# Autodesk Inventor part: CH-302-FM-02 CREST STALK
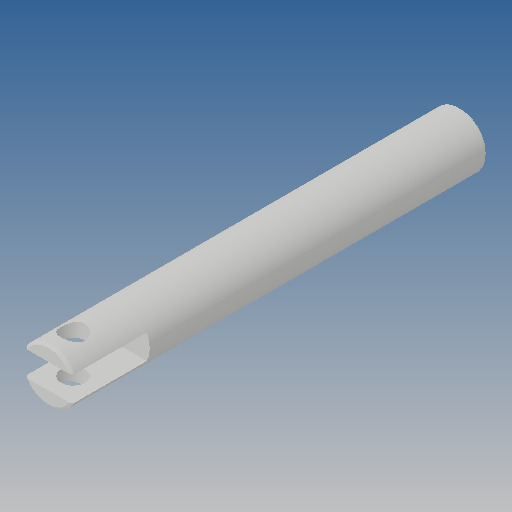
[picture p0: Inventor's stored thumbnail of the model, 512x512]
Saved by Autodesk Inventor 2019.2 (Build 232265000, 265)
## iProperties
Created: 2013-03
Part Number: CH-302-FM-02 CREST STALK
Material: Ogólny
Document SubType Name: Modeling
Designer: CADENGINEERING4
Density: 1 g/cm^3
Appearance: Domyślna
Author: CADENGINEERING4
Revision Number: ÈÎºÎ
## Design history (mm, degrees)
feature "ÇÐ³ý-É¨Ãè1"
node "Bryła1"
